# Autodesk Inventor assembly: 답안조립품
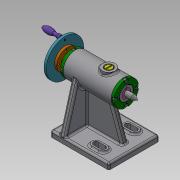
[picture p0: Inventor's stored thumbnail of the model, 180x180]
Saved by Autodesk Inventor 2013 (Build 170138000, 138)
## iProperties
Created: 2019-10
Part Number: 답안조립품
Document SubType Name: Assembly
Designer: Administrator
Author: Administrator
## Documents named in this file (18)
- C:\Documents and Settings\Administrator\바탕 화면\491004V1028\답안조립품.iam
- C:\Documents and Settings\Administrator\바탕 화면\491004V1028\본체.ipt
- C:\Documents and Settings\Administrator\바탕 화면\491004V1028\나사축.ipt
- C:\Documents and Settings\Administrator\바탕 화면\491004V1028\부시.ipt
- C:\Documents and Settings\Administrator\바탕 화면\491004V1028\슬리브.ipt
- C:\Documents and Settings\Administrator\바탕 화면\491004V1028\중공축.ipt
- C:\Documents and Settings\Administrator\바탕 화면\491004V1028\센터홀더.ipt
- C:\Documents and Settings\Administrator\바탕 화면\491004V1028\멈춤나사 M3.ipt
- C:\Documents and Settings\Administrator\바탕 화면\491004V1028\센터.ipt
- C:\Documents and Settings\Administrator\바탕 화면\491004V1028\커버.ipt
- C:\Documents and Settings\Administrator\바탕 화면\491004V1028\키 4 x 4 x 10.ipt
- C:\Documents and Settings\Administrator\바탕 화면\491004V1028\나사.ipt
- C:\Documents and Settings\Administrator\바탕 화면\491004V1028\볼트 M3.ipt
- C:\Documents and Settings\Administrator\바탕 화면\491004V1028\플랜지.ipt
- C:\Documents and Settings\Administrator\바탕 화면\491004V1028\돌림판.ipt
- C:\Documents and Settings\Administrator\바탕 화면\491004V1028\핸들.ipt
- C:\Documents and Settings\Administrator\바탕 화면\491004V1028\와셔.ipt
- C:\Documents and Settings\Administrator\바탕 화면\491004V1028\너트 M8.ipt
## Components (2 placed, 2 different names)
1. 플랜지:1
2. 핸들:1
